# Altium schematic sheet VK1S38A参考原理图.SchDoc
size A4
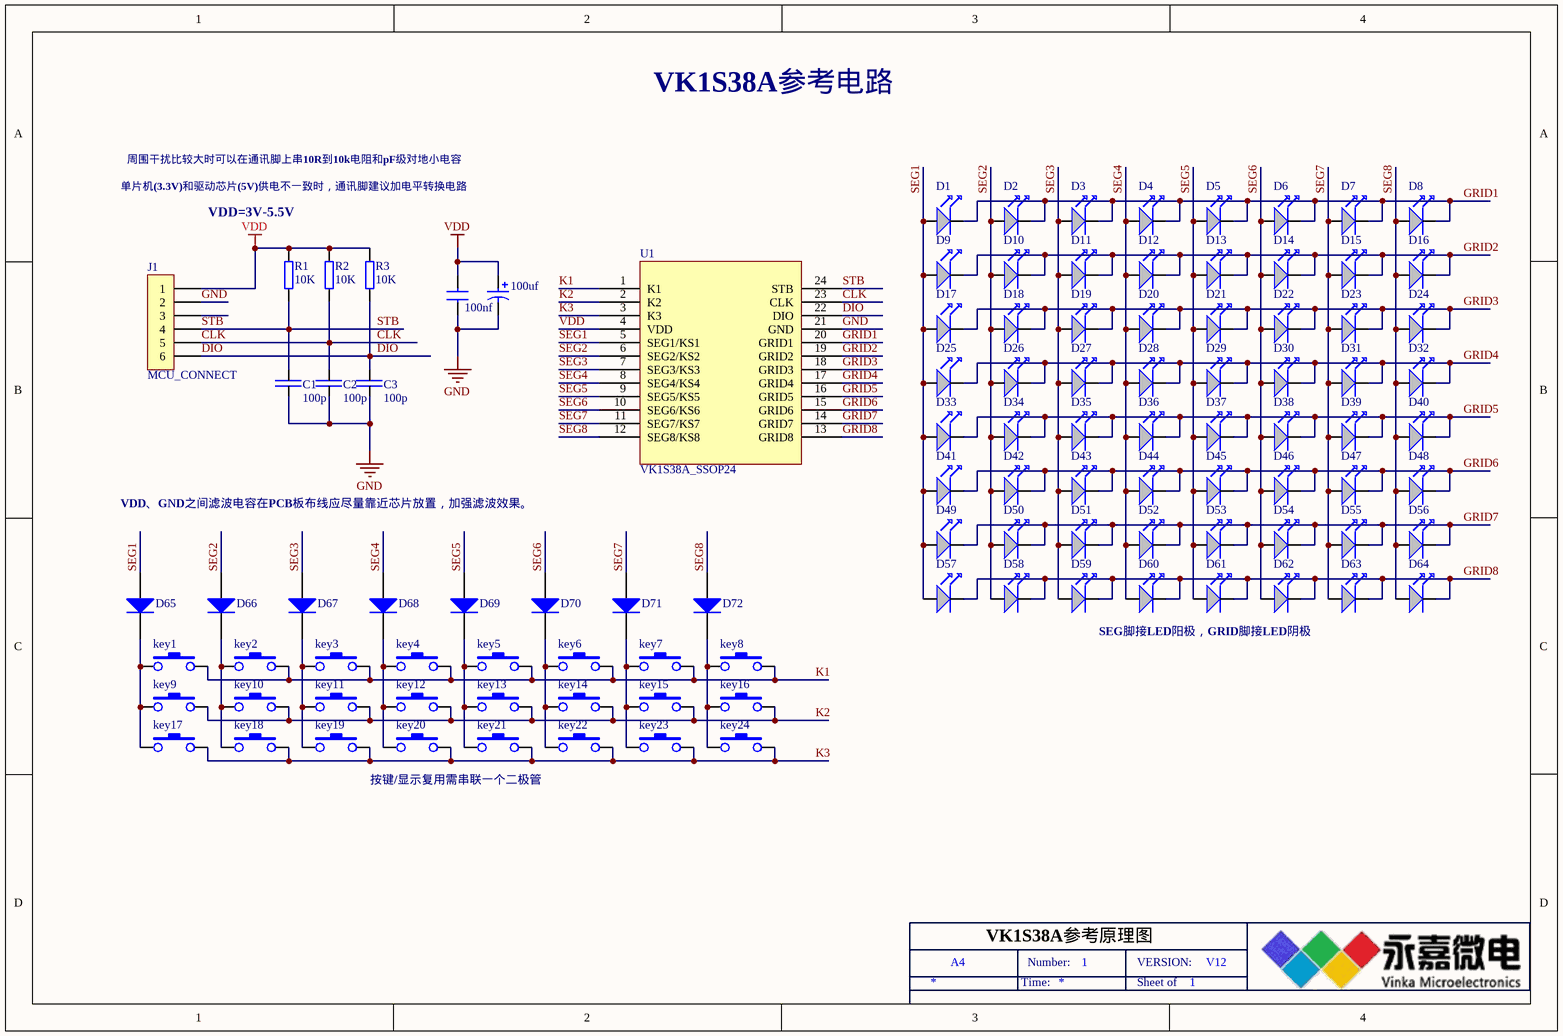
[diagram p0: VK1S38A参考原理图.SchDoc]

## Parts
100nf  CAP  (value not drawn)
100uf  CAP2  (value not drawn)
C1  100p  [C0603]
C2  100p  [C0603]
C3  100p  [C0603]
D1  (no value)  [1206-LED]
D2  (no value)  [1206-LED]
D3  (no value)  [1206-LED]
D4  (no value)  [1206-LED]
D5  (no value)  [1206-LED]
D6  (no value)  [1206-LED]
D7  (no value)  [1206-LED]
D8  (no value)  [1206-LED]
D9  (no value)  [1206-LED]
D10  (no value)  [1206-LED]
D11  (no value)  [1206-LED]
D12  (no value)  [1206-LED]
D13  (no value)  [1206-LED]
D14  (no value)  [1206-LED]
D15  (no value)  [1206-LED]
D16  (no value)  [1206-LED]
D17  (no value)  [1206-LED]
D18  (no value)  [1206-LED]
D19  (no value)  [1206-LED]
D20  (no value)  [1206-LED]
D21  (no value)  [1206-LED]
D22  (no value)  [1206-LED]
D23  (no value)  [1206-LED]
D24  (no value)  [1206-LED]
D25  (no value)  [1206-LED]
D26  (no value)  [1206-LED]
D27  (no value)  [1206-LED]
D28  (no value)  [1206-LED]
D29  (no value)  [1206-LED]
D30  (no value)  [1206-LED]
D31  (no value)  [1206-LED]
D32  (no value)  [1206-LED]
D33  (no value)  [1206-LED]
D34  (no value)  [1206-LED]
D35  (no value)  [1206-LED]
D36  (no value)  [1206-LED]
D37  (no value)  [1206-LED]
D38  (no value)  [1206-LED]
D39  (no value)  [1206-LED]
D40  (no value)  [1206-LED]
D41  (no value)  [1206-LED]
D42  (no value)  [1206-LED]
D43  (no value)  [1206-LED]
D44  (no value)  [1206-LED]
D45  (no value)  [1206-LED]
D46  (no value)  [1206-LED]
D47  (no value)  [1206-LED]
D48  (no value)  [1206-LED]
D49  (no value)  [1206-LED]
D50  (no value)  [1206-LED]
D51  (no value)  [1206-LED]
D52  (no value)  [1206-LED]
D53  (no value)  [1206-LED]
D54  (no value)  [1206-LED]
D55  (no value)  [1206-LED]
D56  (no value)  [1206-LED]
D57  (no value)  [1206-LED]
D58  (no value)  [1206-LED]
D59  (no value)  [1206-LED]
D60  (no value)  [1206-LED]
D61  (no value)  [1206-LED]
D62  (no value)  [1206-LED]
D63  (no value)  [1206-LED]
D64  (no value)  [1206-LED]
D65  Diode 1N4003  [DO-41]  (value not drawn)
D66  Diode 1N4003  [DO-41]  (value not drawn)
D67  Diode 1N4003  [DO-41]  (value not drawn)
D68  Diode 1N4003  [DO-41]  (value not drawn)
D69  Diode 1N4003  [DO-41]  (value not drawn)
D70  Diode 1N4003  [DO-41]  (value not drawn)
D71  Diode 1N4003  [DO-41]  (value not drawn)
D72  Diode 1N4003  [DO-41]  (value not drawn)
J1  MCU_CONNECT
key1  KEY  [AN12]  (value not drawn)
key2  KEY  [AN12]  (value not drawn)
key3  KEY  [AN12]  (value not drawn)
key4  KEY  [AN12]  (value not drawn)
key5  KEY  [AN12]  (value not drawn)
key6  KEY  [AN12]  (value not drawn)
key7  KEY  [AN12]  (value not drawn)
key8  KEY  [AN12]  (value not drawn)
key9  KEY  [AN12]  (value not drawn)
key10  KEY  [AN12]  (value not drawn)
key11  KEY  [AN12]  (value not drawn)
key12  KEY  [AN12]  (value not drawn)
key13  KEY  [AN12]  (value not drawn)
key14  KEY  [AN12]  (value not drawn)
key15  KEY  [AN12]  (value not drawn)
key16  KEY  [AN12]  (value not drawn)
key17  KEY  [AN12]  (value not drawn)
key18  KEY  [AN12]  (value not drawn)
key19  KEY  [AN12]  (value not drawn)
key20  KEY  [AN12]  (value not drawn)
key21  KEY  [AN12]  (value not drawn)
key22  KEY  [AN12]  (value not drawn)
key23  KEY  [AN12]  (value not drawn)
key24  KEY  [AN12]  (value not drawn)
R1  10K  [0603-R]
R2  10K  [0603-R]
R3  10K  [0603-R]
U1  VK1S38A_SSOP24

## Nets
GND: 100nf.2 100uf.2 C1.2 C2.2 C3.2 J1.2 U1.21(GND)
VDD: 100nf.1 100uf.1 J1.1 R1.1 R2.1 R3.1 U1.4(VDD)
CLK: C2.1 J1.5 R2.2 U1.23(CLK)
DIO: C3.1 J1.6 R3.2 U1.22(DIO)
GRID1: D1.2 D2.2 D3.2 D4.2 D5.2 D6.2 D7.2 D8.2 U1.20(GRID1)
GRID2: D9.2 D10.2 D11.2 D12.2 D13.2 D14.2 D15.2 D16.2 U1.19(GRID2)
GRID3: D17.2 D18.2 D19.2 D20.2 D21.2 D22.2 D23.2 D24.2 U1.18(GRID3)
GRID4: D25.2 D26.2 D27.2 D28.2 D29.2 D30.2 D31.2 D32.2 U1.17(GRID4)
GRID5: D33.2 D34.2 D35.2 D36.2 D37.2 D38.2 D39.2 D40.2 U1.16(GRID5)
GRID6: D41.2 D42.2 D43.2 D44.2 D45.2 D46.2 D47.2 D48.2 U1.15(GRID6)
GRID7: D49.2 D50.2 D51.2 D52.2 D53.2 D54.2 D55.2 D56.2 U1.14(GRID7)
GRID8: D57.2 D58.2 D59.2 D60.2 D61.2 D62.2 D63.2 D64.2 U1.13(GRID8)
K1: key1.2 key2.2 key3.2 key4.2 key5.2 key6.2 key7.2 key8.2 U1.1(K1)
K2: key9.2 key10.2 key11.2 key12.2 key13.2 key14.2 key15.2 key16.2 U1.2(K2)
K3: key17.2 key18.2 key19.2 key20.2 key21.2 key22.2 key23.2 key24.2 U1.3(K3)
SEG1: D1.1 D9.1 D17.1 D25.1 D33.1 D41.1 D49.1 D57.1 D65.1(A) U1.5(SEG1/KS1)
SEG2: D2.1 D10.1 D18.1 D26.1 D34.1 D42.1 D50.1 D58.1 D66.1(A) U1.6(SEG2/KS2)
SEG3: D3.1 D11.1 D19.1 D27.1 D35.1 D43.1 D51.1 D59.1 D67.1(A) U1.7(SEG3/KS3)
SEG4: D4.1 D12.1 D20.1 D28.1 D36.1 D44.1 D52.1 D60.1 D68.1(A) U1.8(SEG4/KS4)
SEG5: D5.1 D13.1 D21.1 D29.1 D37.1 D45.1 D53.1 D61.1 D69.1(A) U1.9(SEG5/KS5)
SEG6: D6.1 D14.1 D22.1 D30.1 D38.1 D46.1 D54.1 D62.1 D70.1(A) U1.10(SEG6/KS6)
SEG7: D7.1 D15.1 D23.1 D31.1 D39.1 D47.1 D55.1 D63.1 D71.1(A) U1.11(SEG7/KS7)
SEG8: D8.1 D16.1 D24.1 D32.1 D40.1 D48.1 D56.1 D64.1 D72.1(A) U1.12(SEG8/KS8)
STB: C1.1 J1.4 R1.2 U1.24(STB)
NetD65_2: D65.2(K) key1.1 key9.1 key17.1
NetD66_2: D66.2(K) key2.1 key10.1 key18.1
NetD67_2: D67.2(K) key3.1 key11.1 key19.1
NetD68_2: D68.2(K) key4.1 key12.1 key20.1
NetD69_2: D69.2(K) key5.1 key13.1 key21.1
NetD70_2: D70.2(K) key6.1 key14.1 key22.1
NetD71_2: D71.2(K) key7.1 key15.1 key23.1
NetD72_2: D72.2(K) key8.1 key16.1 key24.1

Not connected (* = marked no-connect by the designer): J1 3

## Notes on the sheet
- VK1S38A参考电路
- 周围干扰比较大时可以在通讯脚上串10R到10k电阻和pF级对地小电容
- 单片机(3.3V)和驱动芯片(5V)供电不一致时，通讯脚建议加电平转换电路
- VDD=3V-5.5V
- VDD、GND之间滤波电容在PCB板布线应尽量靠近芯片放置，加强滤波效果。
- SEG脚接LED阳极，GRID脚接LED阴极
- 按键/显示复用需串联一个二极管
- A4
- VK1S38A参考原理图
- Time:
- Number:
- 1
- Sheet of
- VERSION:
- V12

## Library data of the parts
100nf = CAP: Capacitor
100uf = CAP2: Bi-Polar Capacitor
C1-C3 = CAP: 分类: 电容; 参数: 20%,50V,X5R
D1-D64 = LED: Text Field1: 30; Text Field2: 20
D65-D72 = Diode 1N4003: 1 Amp General Purpose Rectifier
J1 = CON6: Connector
R1-R3 = RES: Resistor
U1 = VK1S38A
